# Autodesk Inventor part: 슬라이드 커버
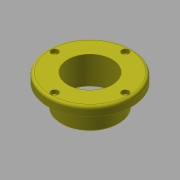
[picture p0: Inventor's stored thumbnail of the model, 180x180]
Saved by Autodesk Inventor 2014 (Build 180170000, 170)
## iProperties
Created: 2015-10
Part Number: 슬라이드 커버
Document SubType Name: Modeling
Designer: mdu
Density: 7.86 g/cm^3
Material: 강철, 연강
Mass: 633.012 g
Surface Area: 239.629 cm^2
Volume: 80.5358 cm^3
Appearance: Canary
Author: mdu
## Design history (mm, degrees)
sketch "스케치1"
  geometry: C1 r 47.5 at (0, 0); C2 r 32.5 at (0, 0); 1 further point
  constraints: 2 centre point, 2 coincident
  dimensions: "d33" = 95 diameter of C1; "d35" = 65 diameter of C2
extrude "돌출1" new body sketch "스케치1" distance "d0" = 10; taper "d1" = 0 deg
extrude "돌출2" join sketch "스케치1" distance "d2" = 25; taper "d3" = 0 deg
hole "구멍1" diameter "d6" = 50; stored, may be unused: countersink angle "d10" = 90 deg, drill point angle "d12" = 118 deg; dims "d4" = 10, "d5" = 10, "d7" = 6, "d8" = 4, "d9" = 2, "d11" = 8
sketch "스케치2" dims "d36" = 80
  geometry: 4 further points
  constraints: 2 coincident, 2 vertical alignment, 2 other
hole "구멍2" sketch "스케치2" at (0, 40) diameter "d13" = 4.5; stored, may be unused: countersink angle "d17" = 90 deg, drill point angle "d19" = 118 deg; dims "d14" = 6, "d15" = 8, "d16" = 4.4, "d18" = 8
fillet "모깎기1" dims "d23" = 3
chamfer "모따기1" distance "d24" = 1; stored, may be unused: second distance "d25" = 2, angle "d26" = 45 deg
sketch "스케치3"
  geometry: C1 r 25 at (0, 0); C2 r 30 at (0, 0); C3 r 26 at (0, 0) reference; 1 further point
  constraints: 2 centre point, 2 coincident
  dimensions: "d27" = 60 diameter of C2
extrude "돌출3" cut sketch "스케치3" distance "d28" = 3; taper "d29" = 0 deg
chamfer "모따기2" distance "d30" = 1; stored, may be unused: second distance "d31" = 2, angle "d32" = 45 deg
node "솔리드1"
pattern_circular "원형 패턴1" dims angle "d21" = 360 deg
